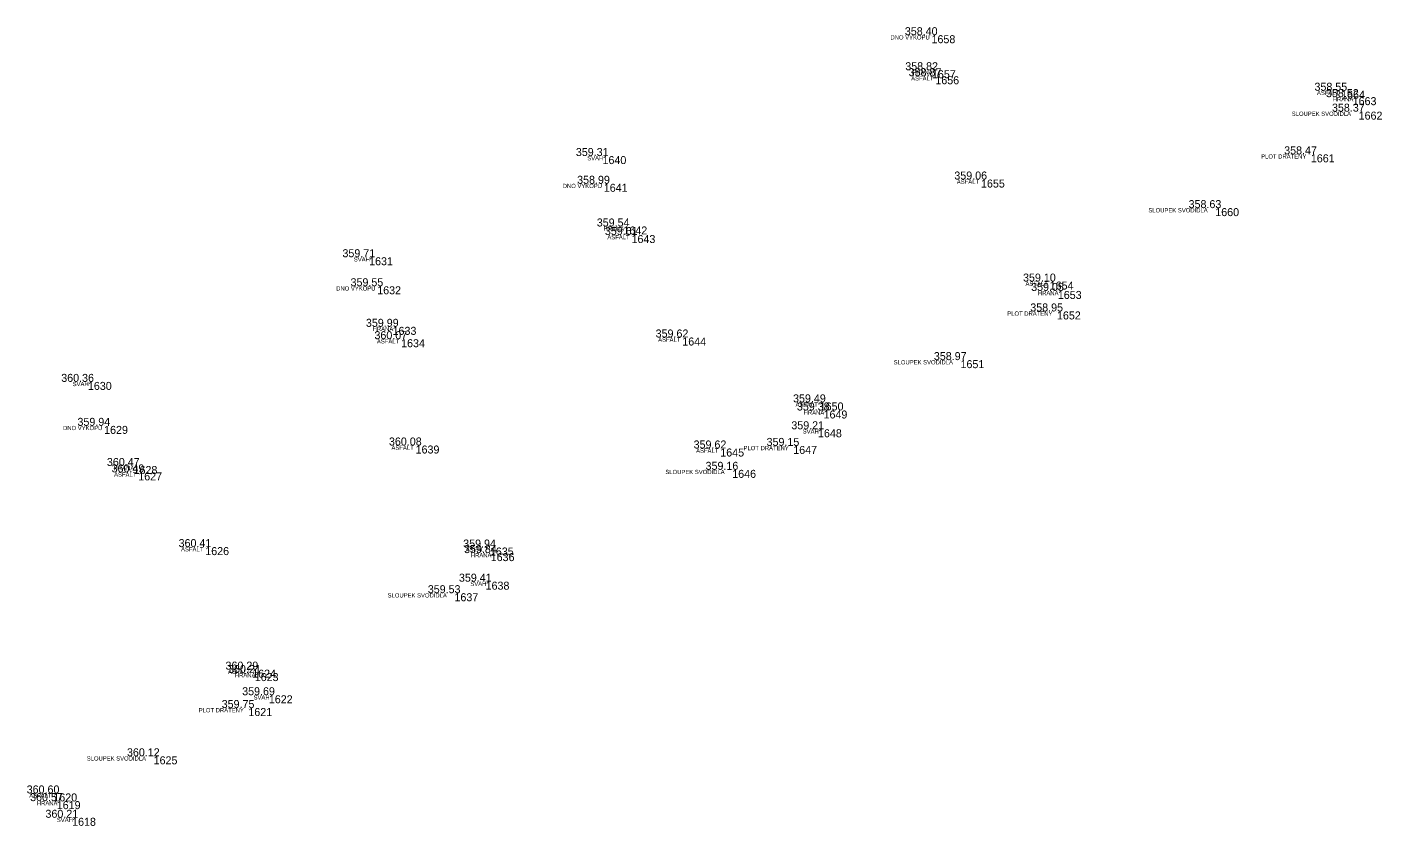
# Model space of a CAD drawing. Extents: x -597865 to -597551, y -1151663 to -1149883.
# Drawn here: x -597642.04 to -597610.28, y -1150346.71 to -1150328 of the extents above; entities that cross this region are included whole.
import ezdxf

# ---------------------------------------------------------------- set-up
doc = ezdxf.new("R2010")
doc.units = 0
for name, color, linetype in [('Vrstva 11', 7, 'Continuous'), ('Vrstva 12', 7, 'Continuous'), ('Vrstva 13', 7, 'Continuous'), ('Vrstva 14', 7, 'Continuous')]:
    doc.layers.add(name, color=color, linetype=linetype)

msp = doc.modelspace()

# ---------------------------------------------------------------- linework, layer by layer
at = {"layer": 'Vrstva 11'}
for p, q in [((-597620.84, -1150328.19), (-597620.84, -1150328.19)), ((-597620.83, -1150329.01), (-597620.83, -1150329.01)), ((-597620.75, -1150329.15), (-597620.75, -1150329.15)), ((-597611.24, -1150329.49), (-597611.24, -1150329.49)), ((-597610.97, -1150329.64), (-597610.97, -1150329.64)), ((-597610.83, -1150329.98), (-597610.83, -1150329.98)), ((-597628.55, -1150331.02), (-597628.55, -1150331.02)), ((-597611.95, -1150330.98), (-597611.95, -1150330.98)), ((-597628.52, -1150331.67), (-597628.52, -1150331.67)), ((-597619.68, -1150331.57), (-597619.68, -1150331.57)), ((-597614.19, -1150332.24), (-597614.19, -1150332.24)), ((-597628.06, -1150332.67), (-597628.06, -1150332.67)), ((-597627.87, -1150332.87), (-597627.87, -1150332.87)), ((-597634.02, -1150333.39), (-597634.02, -1150333.39)), ((-597633.83, -1150334.07), (-597633.83, -1150334.07)), ((-597618.07, -1150333.96), (-597618.07, -1150333.96)), ((-597617.88, -1150334.18), (-597617.88, -1150334.18)), ((-597617.9, -1150334.66), (-597617.9, -1150334.66)), ((-597633.47, -1150335.02), (-597633.47, -1150335.02)), ((-597633.27, -1150335.31), (-597633.27, -1150335.31)), ((-597626.68, -1150335.27), (-597626.68, -1150335.27)), ((-597620.16, -1150335.8), (-597620.16, -1150335.8)), ((-597640.61, -1150336.31), (-597640.61, -1150336.31)), ((-597623.46, -1150336.79), (-597623.46, -1150336.79)), ((-597623.37, -1150336.98), (-597623.37, -1150336.98)), ((-597640.23, -1150337.34), (-597640.23, -1150337.34)), ((-597623.5, -1150337.42), (-597623.5, -1150337.42)), ((-597632.93, -1150337.8), (-597632.93, -1150337.8)), ((-597625.79, -1150337.87), (-597625.79, -1150337.87)), ((-597624.08, -1150337.81), (-597624.08, -1150337.81)), ((-597639.54, -1150338.28), (-597639.54, -1150338.28)), ((-597639.43, -1150338.43), (-597639.43, -1150338.43)), ((-597625.51, -1150338.37), (-597625.51, -1150338.37)), ((-597637.86, -1150340.18), (-597637.86, -1150340.18)), ((-597631.19, -1150340.19), (-597631.19, -1150340.19)), ((-597631.17, -1150340.32), (-597631.17, -1150340.32)), ((-597631.29, -1150340.99), (-597631.29, -1150340.99)), ((-597632.02, -1150341.26), (-597632.02, -1150341.26)), ((-597636.76, -1150343.05), (-597636.76, -1150343.05)), ((-597636.7, -1150343.13), (-597636.7, -1150343.13)), ((-597636.37, -1150343.65), (-597636.37, -1150343.65)), ((-597636.85, -1150343.95), (-597636.85, -1150343.95)), ((-597639.07, -1150345.08), (-597639.07, -1150345.08)), ((-597641.42, -1150345.95), (-597641.42, -1150345.95)), ((-597641.34, -1150346.13), (-597641.34, -1150346.13)), ((-597640.98, -1150346.52), (-597640.98, -1150346.52))]:
    msp.add_line(p, q, dxfattribs=at)

# ---------------------------------------------------------------- texts
at = {"layer": 'Vrstva 12'}
for s, p in [('358.40 ', (-597621.465, -1150328.19)), ('358.82 ', (-597621.455, -1150329.01)), ('358.87 ', (-597621.375, -1150329.15)), ('358.55 ', (-597611.865, -1150329.49)), ('358.52 ', (-597611.595, -1150329.64)), ('358.37 ', (-597611.455, -1150329.98)), ('359.31 ', (-597629.175, -1150331.02)), ('358.47 ', (-597612.575, -1150330.98)), ('358.99 ', (-597629.145, -1150331.67)), ('359.06 ', (-597620.305, -1150331.57)), ('358.63 ', (-597614.815, -1150332.24)), ('359.54 ', (-597628.685, -1150332.67)), ('359.61 ', (-597628.495, -1150332.87)), ('359.71 ', (-597634.645, -1150333.39)), ('359.10 ', (-597618.695, -1150333.96)), ('359.55 ', (-597634.455, -1150334.07)), ('359.05 ', (-597618.505, -1150334.18)), ('358.95 ', (-597618.525, -1150334.66)), ('359.99 ', (-597634.095, -1150335.02)), ('360.07 ', (-597633.895, -1150335.31)), ('359.62 ', (-597627.305, -1150335.27)), ('358.97 ', (-597620.785, -1150335.8)), ('360.36 ', (-597641.235, -1150336.31)), ('359.49 ', (-597624.085, -1150336.79)), ('359.38 ', (-597623.995, -1150336.98)), ('359.94 ', (-597640.855, -1150337.34)), ('359.21 ', (-597624.125, -1150337.42)), ('360.08 ', (-597633.555, -1150337.8)), ('359.62 ', (-597626.415, -1150337.87)), ('359.15 ', (-597624.705, -1150337.81)), ('360.47 ', (-597640.165, -1150338.28)), ('359.16 ', (-597626.135, -1150338.37)), ('360.49 ', (-597640.055, -1150338.43)), ('360.41 ', (-597638.485, -1150340.18)), ('359.94 ', (-597631.815, -1150340.19)), ('359.84 ', (-597631.795, -1150340.32)), ('359.53 ', (-597632.645, -1150341.26)), ('359.41 ', (-597631.915, -1150340.99)), ('360.29 ', (-597637.385, -1150343.05)), ('360.21 ', (-597637.325, -1150343.13)), ('359.69 ', (-597636.995, -1150343.65)), ('359.75 ', (-597637.475, -1150343.95)), ('360.12 ', (-597639.695, -1150345.08)), ('360.60 ', (-597642.045, -1150345.95)), ('360.57 ', (-597641.965, -1150346.13)), ('360.21 ', (-597641.605, -1150346.52))]:
    msp.add_text(s, height=0.1875, dxfattribs=at).set_placement(p)
at = {"layer": 'Vrstva 13'}
for s, p in [('1658', (-597620.84, -1150328.377)), ('1657', (-597620.83, -1150329.198)), ('1656', (-597620.75, -1150329.338)), ('1664', (-597611.24, -1150329.677)), ('1663', (-597610.97, -1150329.828)), ('1662', (-597610.83, -1150330.167)), ('1640', (-597628.55, -1150331.208)), ('1661', (-597611.95, -1150331.167)), ('1641', (-597628.52, -1150331.857)), ('1655', (-597619.68, -1150331.758)), ('1660', (-597614.19, -1150332.427)), ('1642', (-597628.06, -1150332.857)), ('1643', (-597627.87, -1150333.058)), ('1631', (-597634.02, -1150333.578)), ('1632', (-597633.83, -1150334.258)), ('1654', (-597618.07, -1150334.147)), ('1653', (-597617.88, -1150334.367)), ('1652', (-597617.9, -1150334.847)), ('1633', (-597633.47, -1150335.208)), ('1634', (-597633.27, -1150335.498)), ('1644', (-597626.68, -1150335.458)), ('1651', (-597620.16, -1150335.988)), ('1630', (-597640.61, -1150336.498)), ('1650', (-597623.46, -1150336.978)), ('1649', (-597623.37, -1150337.167)), ('1629', (-597640.23, -1150337.528)), ('1648', (-597623.5, -1150337.607)), ('1639', (-597632.93, -1150337.988)), ('1645', (-597625.79, -1150338.058)), ('1647', (-597624.08, -1150337.998)), ('1628', (-597639.54, -1150338.468)), ('1627', (-597639.43, -1150338.617)), ('1646', (-597625.51, -1150338.558)), ('1626', (-597637.86, -1150340.367)), ('1635', (-597631.19, -1150340.377)), ('1636', (-597631.17, -1150340.508)), ('1638', (-597631.29, -1150341.177)), ('1637', (-597632.02, -1150341.448)), ('1624', (-597636.76, -1150343.238)), ('1623', (-597636.7, -1150343.318)), ('1622', (-597636.37, -1150343.838)), ('1621', (-597636.85, -1150344.137)), ('1625', (-597639.07, -1150345.268)), ('1620', (-597641.42, -1150346.137)), ('1619', (-597641.34, -1150346.318)), ('1618', (-597640.98, -1150346.708))]:
    msp.add_text(s, height=0.1875, dxfattribs=at).set_placement(p)
at = {"layer": 'Vrstva 14'}
for s, p in [('DNO VYKOPU', (-597621.802, -1150328.29)), ('HRANA', (-597621.297, -1150329.11)), ('ASFALT', (-597621.317, -1150329.25)), ('ASFALT', (-597611.807, -1150329.59)), ('HRANA', (-597611.437, -1150329.74)), ('SLOUPEK SVODIDLA', (-597612.397, -1150330.08)), ('SVAH', (-597628.908, -1150331.12)), ('PLOT DRATENY', (-597613.115, -1150331.08)), ('DNO VYKOPU', (-597629.483, -1150331.77)), ('ASFALT', (-597620.247, -1150331.67)), ('SLOUPEK SVODIDLA', (-597615.757, -1150332.34)), ('HRANA', (-597628.527, -1150332.77)), ('ASFALT', (-597628.437, -1150332.97)), ('SVAH', (-597634.378, -1150333.49)), ('DNO VYKOPU', (-597634.792, -1150334.17)), ('ASFALT', (-597618.637, -1150334.06)), ('HRANA', (-597618.347, -1150334.28)), ('PLOT DRATENY', (-597619.065, -1150334.76)), ('HRANA', (-597633.937, -1150335.12)), ('ASFALT', (-597633.837, -1150335.41)), ('ASFALT', (-597627.247, -1150335.37)), ('SLOUPEK SVODIDLA', (-597621.727, -1150335.9)), ('SVAH', (-597640.968, -1150336.41)), ('ASFALT', (-597624.027, -1150336.89)), ('HRANA', (-597623.837, -1150337.08)), ('DNO VYKOPU', (-597641.193, -1150337.44)), ('SVAH', (-597623.858, -1150337.52)), ('ASFALT', (-597633.497, -1150337.9)), ('ASFALT', (-597626.357, -1150337.97)), ('PLOT DRATENY', (-597625.245, -1150337.91)), ('HRANA', (-597640.007, -1150338.38)), ('ASFALT', (-597639.997, -1150338.53)), ('SLOUPEK SVODIDLA', (-597627.077, -1150338.47)), ('ASFALT', (-597638.427, -1150340.28)), ('ASFALT', (-597631.757, -1150340.29)), ('HRANA', (-597631.637, -1150340.42)), ('SVAH', (-597631.648, -1150341.09)), ('SLOUPEK SVODIDLA', (-597633.587, -1150341.36)), ('ASFALT', (-597637.327, -1150343.15)), ('HRANA', (-597637.167, -1150343.23)), ('SVAH', (-597636.728, -1150343.75)), ('PLOT DRATENY', (-597638.015, -1150344.05)), ('SLOUPEK SVODIDLA', (-597640.637, -1150345.18)), ('ASFALT', (-597641.987, -1150346.05)), ('HRANA', (-597641.807, -1150346.23)), ('SVAH', (-597641.338, -1150346.62))]:
    msp.add_text(s, height=0.1, dxfattribs=at).set_placement(p)

doc.saveas('drawing.dxf')
